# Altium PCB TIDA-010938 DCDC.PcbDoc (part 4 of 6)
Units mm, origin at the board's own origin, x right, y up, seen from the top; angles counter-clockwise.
Board outline 280 x 174.95 mm, 4 copper layers (Top Layer, Layer 1, Layer 2, Bottom Layer), stack 1.787 mm thick; 409 components, 218 nets, 1371 pads, 2268 vias.
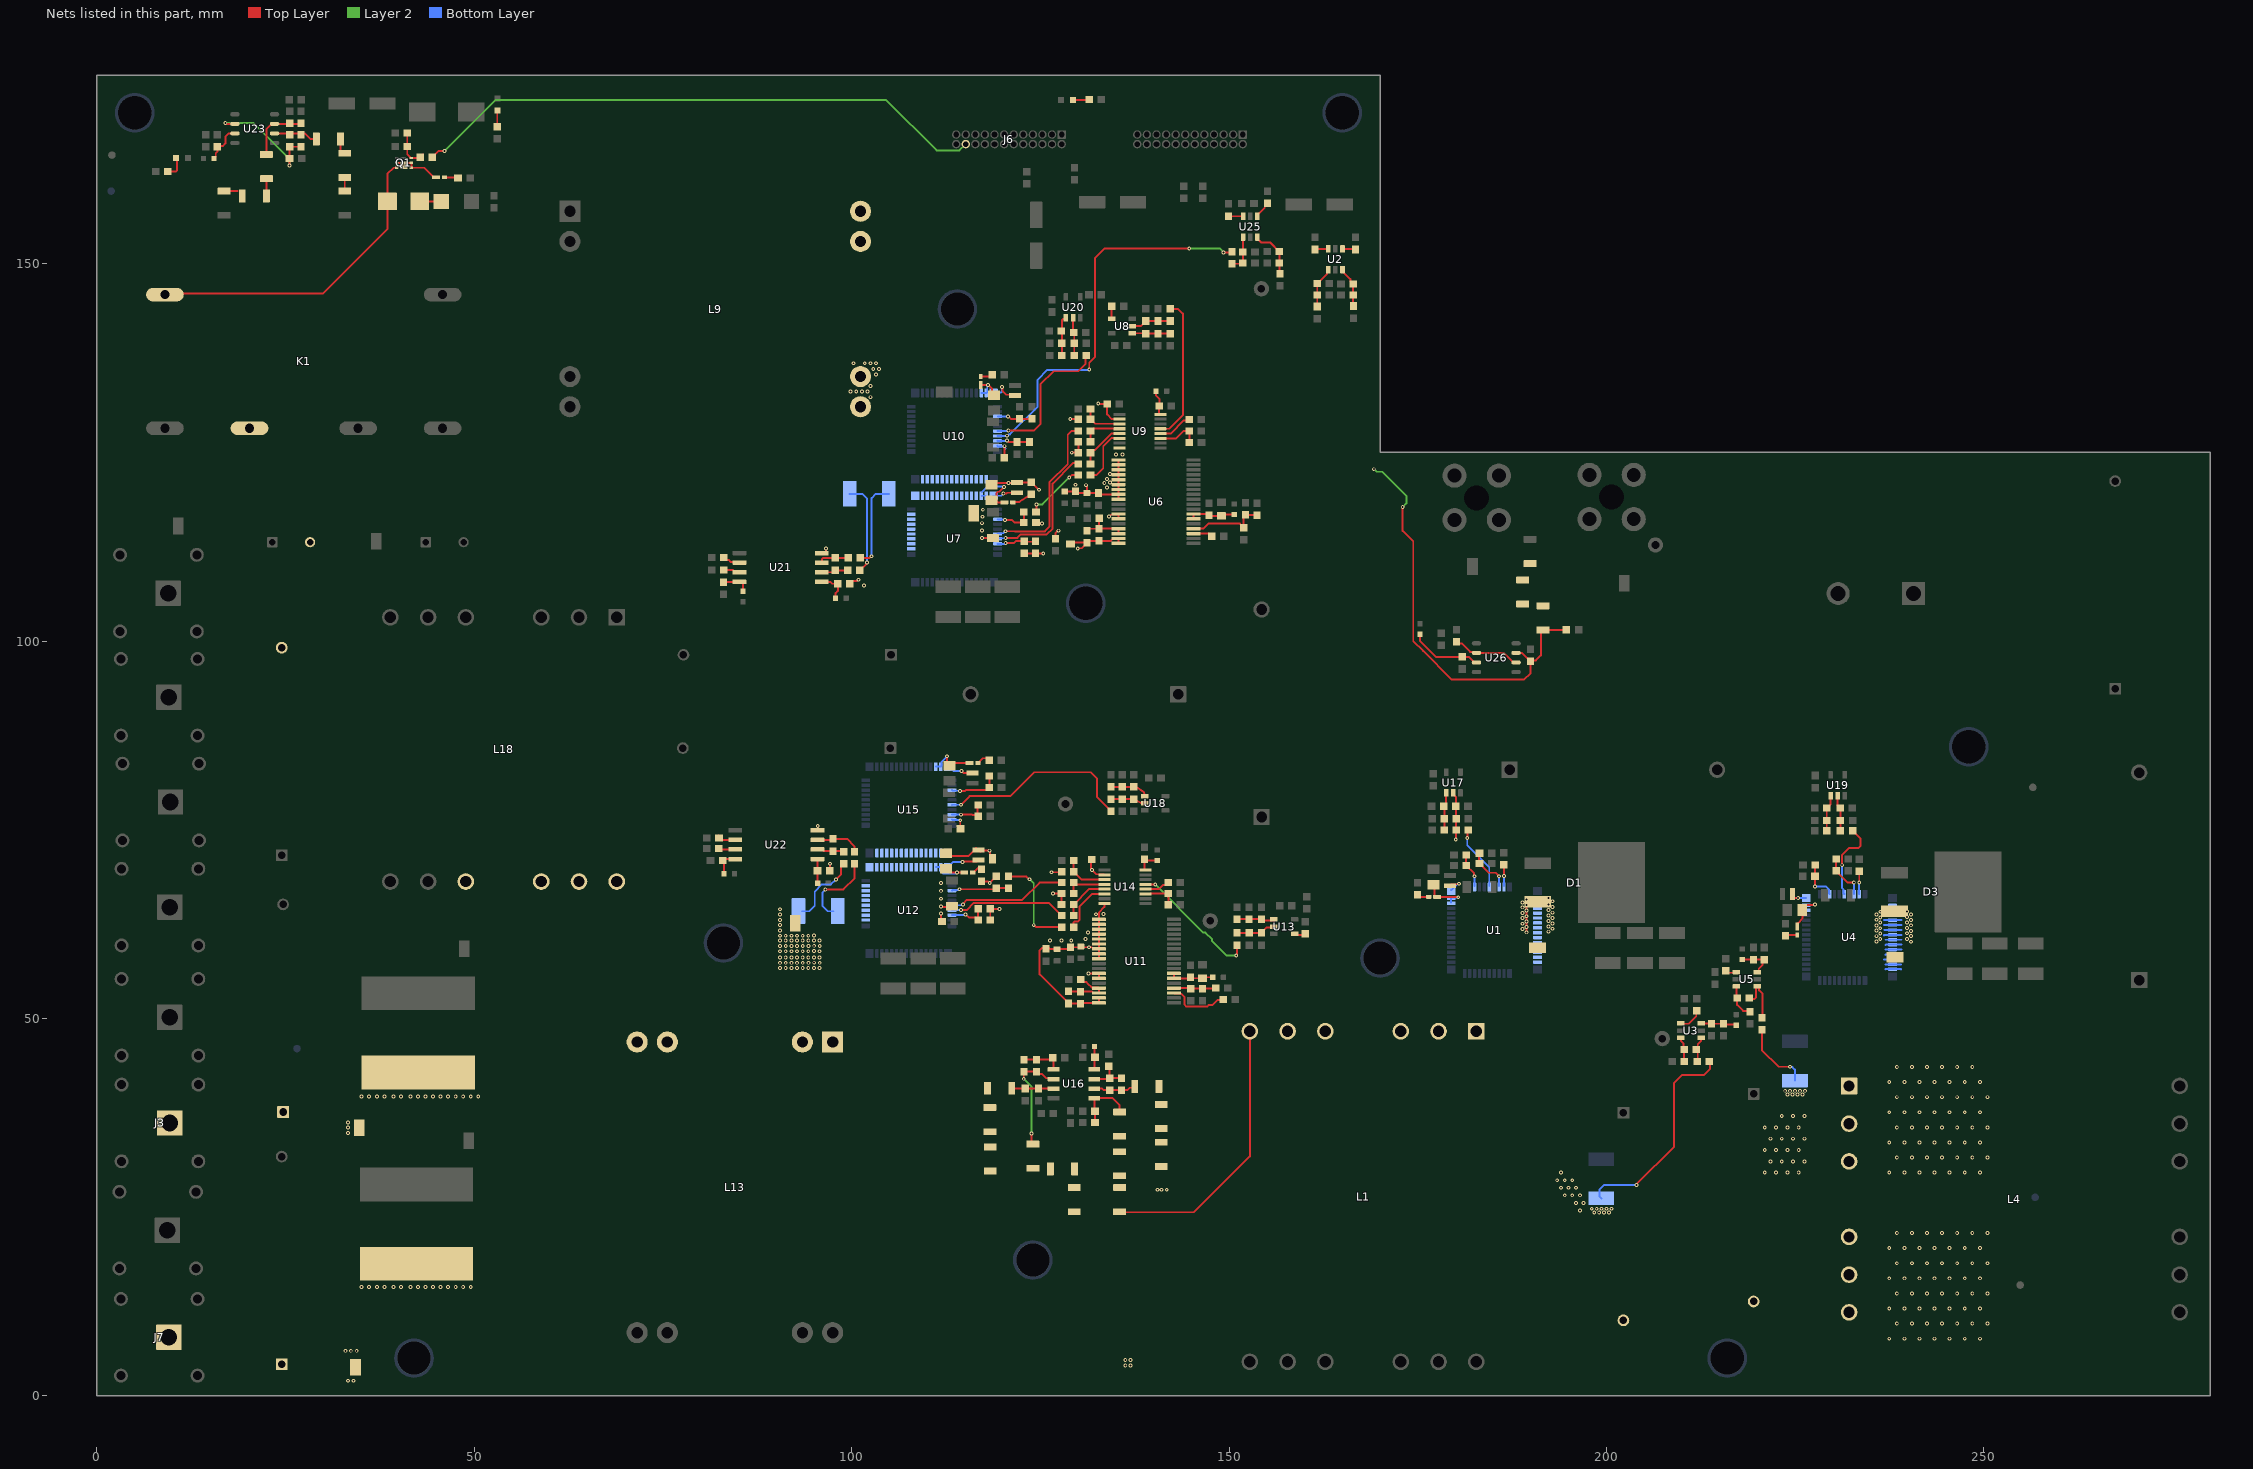
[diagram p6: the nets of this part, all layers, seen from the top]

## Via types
v1: diameter 0.508, hole 0.254, Top Layer to Bottom Layer, tented both sides, 1783 vias
v2: diameter 0.508, hole 0.254, Top Layer to Bottom Layer, 485 vias

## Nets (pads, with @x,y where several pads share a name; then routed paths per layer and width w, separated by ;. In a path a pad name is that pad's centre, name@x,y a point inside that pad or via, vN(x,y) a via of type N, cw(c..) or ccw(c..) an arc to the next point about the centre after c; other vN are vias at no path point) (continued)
IN_PWM_Bat_H1: R24.1 R38.2 | length 8.2
  Top Layer w0.254: R24.1@124.46,116.84 v1(124.46,118.11) ; v1(128.823,121.677) 128.836,121.677 129.158,122 R38.2@129.75,122
  Layer 2 w0.254: v1(124.46,118.11) 125.256,118.11 v1(128.823,121.677)
IN_PWM_Bat_H2: R49.1 R63.2 | length 13.1
  Top Layer w0.254: R49.1@120.494,68.865 R49.1@120.495,68.866 ; R49.1@120.754,68.785 123.155,68.785 123.492,68.449 v1(123.561,68.449) ; v1(124.116,62.355) 124.185,62.355 124.445,62.094 R63.2@127.804,62.094
  Layer 2 w0.254: v1(123.561,68.449) 124.116,67.893 v1(124.116,62.355)
NetC2_2: C2.2 K1.6 L18.9 L18.10 L18.11 L18.12 R88.2
NetC7_2: C7.2 R1.2 U1.45 | length 4.7
  Top Layer w0.254: R1.2@181.401,71.645 C7.2@181.401,70.262 181.426,70.262 182.477,69.211 182.477,68.885 v1(182.526,68.837)
  Bottom Layer w0.254: U1.45@182.526,67.517 v1(182.526,68.837) v1@182.526,68.934
NetC8_2: C8.2 U1.51 | length 2.9
  Top Layer w0.254: C8.2@186.392,70.365 186.426,70.331 v1(186.426,68.885)
  Bottom Layer w0.254: U1.51@186.426,67.517 v1(186.426,68.885)
NetC11_2: C11.2 R3.2 R39.2 U8.1 | length 5.1
  Top Layer w0.254: U8.1@137.189,140.785 138.931,140.785 C11.2@138.968,140.748 140.596,140.748 R3.2@142.259,140.748
NetC12_2: C12.2 R6.2 U1.50 | length 6
  Top Layer w0.254: R6.2@183.176,71.89 183.125,71.839 183.125,70.594 183.549,70.17 183.549,70.145 184.39,69.304 185.302,69.304 v1(185.769,68.836)
  Bottom Layer w0.254: v1(185.769,68.836) 185.773,68.833 185.773,67.52 U1.50@185.776,67.517
NetC13_1: C13.1 D17.1 U1.40 U1.41 | length 6.4
  Top Layer w0.254: C13.1@177.062,67.718 177.225,67.556 177.225,66.232 177.348,66.109 D17.1@177.571,66.109 177.596,66.084 180.341,66.084 v1(180.366,66.059)
  Bottom Layer w0.254: U1.40@179.416,65.367 U1.41@179.416,66.017 ; U1.41@179.416,66.007 179.459,65.964 179.502,66.007 180.245,66.007 180.297,66.059 v1(180.366,66.059)
NetC15_2: C15.2 R5.2 R64.2 U8.2 | length 5.3
  Top Layer w0.254: U8.2@137.189,141.735 138.318,141.735 138.968,142.385 138.968,142.41 R64.2@140.564,142.41 142.193,142.41 R5.2@142.195,142.411
NetC16_1: C16.1 Q1.3 R144.2 R145.1 | length 5.6
  Top Layer w0.254: R145.1@41.102,167.315 C16.1@41.102,165.52 41.102,164.482 41.569,164.016 Q1.3@41.644,164.016 42.866,164.016 R144.2@43.091,164.241 ; R144.2@42.802,164.111 42.827,164.111 R144.2@43.175,164.459
NetC17_1: C17.1 C108.2 FB1.2 U3.6 | length 4.5
  Top Layer w0.254: U3.6@212.575,49.35 213.85,49.35 C108.2@213.9,49.3 215.3,49.3 215.4,49.2 FB1.2@217,49.2
NetC18_1: C18.1 R10.2 U3.4 | length 3.4
  Top Layer w0.254: R10.2@212,44.3 212.1,44.4 212.1,46.6 212.5,47 212.5,47.375 U3.4@212.575,47.45
NetC18_2: C18.2 R9.2 U3.3 | length 3.3
  Top Layer w0.254: U3.3@209.825,47.45 209.9,47.375 209.9,47 210.222,46.678 210.222,45.978 C18.2@210.3,45.9 R9.2@210.3,44.3
NetC21_2: C21.2 U4.51 | length 3
  Top Layer w0.254: v1(233.5,68.006) C21.2@233.5,69.425
  Bottom Layer w0.254: U4.51@233.469,66.475 233.485,66.49 233.485,67.991 v1(233.5,68.006)
NetC22_2: C22.2 R11.2 U4.45 | length 5.5
  Top Layer w0.254: v1(227.625,67.488) 227.625,68.833 C22.2@227.629,68.837 227.629,70.3 R11.2@227.642,70.312
  Bottom Layer w0.254: v1(227.625,67.488) 229.069,67.488 229.471,67.086 229.471,66.573 U4.45@229.569,66.475
NetC25_2: C25.2 R13.2 R156.2 U13.1 | length 5.1
  Top Layer w0.254: R13.2@151.043,63.151 R156.2@152.66,63.151 C25.2@154.276,63.151 154.449,62.978 U13.1@156.055,62.978
NetC26_2: C26.2 R16.2 U4.50 | length 5.6
  Top Layer w0.254: C26.2@230.434,69.565 R16.2@230.434,71.111 ; C26.2@230.805,69.19 231.989,68.006 v1(232.775,68.006)
  Bottom Layer w0.254: v1(232.775,68.006) 232.797,67.984 232.797,66.497 U4.50@232.819,66.475
NetC27_1: C27.1 D18.1 U4.40 U4.41 | length 6.2
  Top Layer w0.254: D18.1@225.352,62.085 225.402,62.135 225.402,62.644 225.966,63.207 C27.1@225.966,64.365 225.966,64.53 226.474,65.038 227.357,65.038 227.409,65.09 v1@227.478,65.09
  Bottom Layer w0.254: U4.40@226.459,64.325 U4.41@226.459,64.975 226.525,65.041 227.429,65.041 v1@227.478,65.09
  other v1: 227.64,65.09
NetC29_2: C29.2 R15.2 R157.2 U13.2 | length 5.3
  Top Layer w0.254: R15.2@151.045,61.328 R157.2@152.661,61.328 C29.2@154.278,61.328 154.278,61.353 154.953,62.028 U13.2@156.055,62.028
NetC31_2: C31.2 C32.1 FB2.2 U5.6 | length 4.9
  Top Layer w0.254: FB2.2@218,57.8 C32.1@219.5,57.8 220.8,57.8 220.668,57.668 220.668,57.068 220.182,56.582 220.182,56.223 220.009,56.05 U5.6@219.975,56.05
NetC33_1: C33.1 R71.2 U5.4 | length 7
  Top Layer w0.254: C33.1@218.9,52.7 219,52.6 219.651,52.6 219.8,52.749 219.8,54.077 220.227,54.077 220.227,53.718 220.7,53.245 220.7,50.2 R71.2@220.6,50.1
NetC33_2: C33.2 R20.2 U5.3 | length 4.5
  Top Layer w0.254: U5.3@217.225,54.15 217.225,52.775 C33.2@217.3,52.7 217.3,51.8 218.1,51 218.9,51 R20.2@219,51.1
NetC35_2: C35.2 R24.2 U7.45 | length 5
  Top Layer w0.254: v1(120.319,116.034) 121.25,116.034 121.583,115.702 C35.2@122.818,115.702 ; C35.2@122.818,115.758 R24.2@122.818,117.117
  Bottom Layer w0.254: U7.45@119.333,116.144 119.36,116.117 120.293,116.117 v1@120.319,116.091
NetC39_2: C39.2 C43.2 FB4.2 U6.6 U6.7 | length 5.9
  Top Layer w0.254: U6.6@145.299,116.19 U6.7@145.299,116.84 147.178,116.84 147.328,116.69 147.428,116.59 C39.2@148.966,116.59 149.166,116.79 FB4.2@150.383,116.79
NetC42_1: C42.1 R23.2 R29.1 U6.33 U6.34 | length 6.3
  Top Layer w0.254: R29.1@131.18,114.884 C42.1@132.78,114.884 ; R23.2@132.78,116.39 C42.1@132.78,114.884 ; U6.34@135.349,114.24 U6.33@135.349,114.89 132.785,114.89 C42.1@132.78,114.884
NetC44_1: C44.1 R58.2 U21.2 | length 3.5
  Top Layer w0.254: U21.2@96.028,109.124 97.537,109.124 C44.1@97.825,109.412 ; C44.1@97.988,109.594 98.208,109.374 R58.2@99.465,109.374
NetC44_2: C44.2 R56.2 U21.3 | length 4.1
  Top Layer w0.254: U21.3@96.028,110.394 96.052,110.418 96.052,110.863 96.201,111.012 C44.2@97.825,111.012 99.52,111.012 R56.2@99.556,111.048
NetC45_2: C45.2 R32.2 U7.50 | length 4.7
  Top Layer w0.254: v1(120.397,112.975) 121.48,112.975 121.757,113.251 122.801,113.251 C45.2@122.846,113.206 ; C45.2@122.856,113.161 R32.2@123.892,113.161
  Bottom Layer w0.254: U7.50@119.333,112.894 119.341,112.886 120.239,112.886 120.328,112.975 v1(120.397,112.975)
NetC46_1: C46.1 D19.1 U7.40 U7.41 | length 8
  Top Layer w0.254: C46.1@118.535,118.667 118.581,118.667 118.924,119.01 119.009,119.01 119.174,119.175 119.174,119.619 119.342,119.787 119.541,119.787 v2(120.159,120.404) ; C46.1@118.983,118.95 118.983,118.883 119.208,118.659 119.208,118.525 119.357,118.376 D19.1@120.234,118.376
  Bottom Layer w0.254: U7.40@117.249,119.749 117.977,120.477 119.906,120.477 119.931,120.453 120.11,120.453 v2(120.159,120.404) ; U7.40@117.25,119.25 117.254,119.254 U7.41@117.825,119.254
NetC47_2: C47.2 R25.2 R27.2 U6.4 | length 10.3
  Top Layer w0.254: U6.4@145.299,114.89 146.605,114.89 147.296,115.58 151.392,115.58 151.56,115.413 151.585,115.413 C47.2@151.933,115.065 ; C47.2@151.933,115.04 C47.2@151.933,115.065 ; R27.2@153.431,116.69 153.416,116.705 151.948,116.705 151.933,116.69 C47.2@151.933,115.065
NetC48_1: C48.1 FB5.2 U21.1 | length 4.4
  Top Layer w0.254: U21.1@96.028,107.854 97.176,107.854 97.433,107.597 98.005,107.597 98.081,107.522 C48.1@98.156,107.597 98.156,106.649 97.863,106.356 FB5.2@97.863,105.681 ; FB5.2@98.009,105.609 FB5.2@98.081,105.681
NetC49_1: C49.1 FB12.2 U21.8 | length 3.7
  Top Layer w0.254: C49.1@83,107.8 83.054,107.854 85.408,107.854 85.581,107.681 FB12.2@85.581,106.608
NetC50_2: C50.2 FB9.2 U9.16 | length 3.4
  Top Layer w0.254: FB9.2@140.323,133.117 140.323,132.516 140.76,132.078 140.76,131.206 C50.2@140.716,131.162 140.716,130.115 140.794,130.037 U9.16@140.893,130.037
NetC53_1: C53.1 R96.2 U22.2 | length 3.6
  Top Layer w0.254: U22.2@95.464,72.39 96.064,72.39 96.275,72.18 C53.1@97.505,72.18 R96.2@98.945,72.18
NetC53_2: C53.2 R67.2 U22.3 | length 6.1
  Top Layer w0.254: U22.3@95.464,73.66 97.386,73.66 C53.2@97.505,73.78 99.384,73.78 100.36,72.804 100.36,72.445 100.522,72.283 R67.2@100.661,72.283
NetC54_2: C54.2 R155.1 U9.5 | length 5.8
  Top Layer w0.254: R155.1@131.639,123.463 C54.2@131.639,124.963 131.987,125.311 132.227,125.311 134.413,127.497 U9.5@134.864,127.497
NetC55_2: C55.2 R34.1 U9.3 | length 5.3
  Top Layer w0.254: R34.1@131.639,130.763 C55.2@131.639,129.389 131.664,129.389 132.254,128.8 U9.3@135.356,128.8
NetC56_1: C56.1 FB14.2 U22.1 | length 3.2
  Top Layer w0.254: FB14.2@95.451,67.923 95.451,69.547 C56.1@95.464,69.561 U22.1@95.464,71.12
NetC57_1: C57.1 FB13.2 U22.8 | length 3.8
  Top Layer w0.254: C57.1@82.839,71.12 U22.8@84.564,71.12 ; FB13.2@83.068,69.18 83.068,70.741 C57.1@82.889,70.92 C57.1@83.089,71.12
NetC58_2: C58.2 R37.2 U9.11 | length 5.8
  Top Layer w0.254: U9.11@140.893,126.862 142.986,126.862 143.981,127.857 C58.2@144.731,127.857 144.744,127.845 R37.2@144.744,126.319
NetC61_2: C61.2 U10.51 | length 2.6
  Top Layer w0.254: C61.2@120.1,124.563 120.238,124.701 v1(120.238,125.823)
  Bottom Layer w0.254: U10.51@119.28,125.902 119.409,125.773 120.133,125.773 120.412,125.493
NetC62_2: C62.2 R40.2 U10.45 | length 4.7
  Top Layer w0.254: v1(120.704,129.767) 120.772,129.767 121.14,129.399 123.807,129.399 R40.2@123.865,129.457
  Bottom Layer w0.254: U10.45@119.354,129.771 119.356,129.769 120.702,129.769 v1(120.704,129.767)
NetC63_1: C63.1 R100.2 R104.1 U16.6 | length 5.6
  Top Layer w0.254: U16.6@132.144,40.703 133.195,40.703 133.398,40.5 C63.1@134.181,40.5 136.5,40.5 136.818,40.818 137.318,40.818 R100.2@137.5,41
NetC63_2: C63.2 R87.1 R104.2 U16.7 | length 5.3
  Top Layer w0.254: U16.7@132.144,41.973 134.053,41.973 C63.2@134.181,42.1 ; R87.1@134.064,43.653 134.181,43.536 C63.2@134.181,42.1 ; R104.2@135.75,42.1 C63.2@134.181,42.1
NetC64_2: C64.2 R45.2 U10.50 | length 4.3
  Top Layer w0.254: v1@120.584,126.555 120.639,126.555 120.819,126.376 R45.2@123.555,126.376
  Bottom Layer w0.254: U10.50@119.28,126.552 119.294,126.538 120.553,126.538 v1(120.571,126.555)
NetC65_1: C65.1 D20.1 U10.40 U10.41 | length 4.4
  Top Layer w0.254: D20.1@117.091,133.931 v1(118.065,133.931) 118.118,133.931 118.593,133.456 118.593,132.834 C65.1@118.837,132.589
  Bottom Layer w0.254: U10.40@117.214,132.881 117.864,132.881 117.962,132.979 117.962,133.759 118.065,133.862 v1(118.065,133.931)
NetC66_1: C66.1 R103.2 R107.1 U16.2 | length 14.4
  Top Layer w0.254: v1(122.795,42) 122.795,42.92 R107.1@122.825,42.95 C66.1@124.5,42.95 124.828,42.622 125.225,42.622 125.771,42.075 126.642,42.075 U16.2@126.744,41.973 ; v1(123.825,34.75) 123.825,33.525 R103.2@124,33.35
  Layer 2 w0.254: v1(122.795,42) 123.825,40.97 v1(123.825,34.75)
NetC66_2: C66.2 R86.1 R107.2 U16.1 | length 5.5
  Top Layer w0.254: R107.2@122.825,44.55 C66.2@124.5,44.55 126.412,44.55 R86.1@126.654,44.793 126.744,44.703 U16.1@126.744,43.243
NetC67_1: C67.1 R75.2 R79.2 U17.1 | length 5
  Top Layer w0.254: R75.2@178.515,74.959 R79.2@178.515,76.459 178.515,78.105 178.76,78.35 U17.1@178.76,79.878
NetC69_2: C69.2 R49.2 U12.45 | length 7.2
  Top Layer w0.254: v1(114.287,67.114) 119.01,67.114 C69.2@119.152,67.256 120.381,67.256 R49.2@120.389,67.265
  Bottom Layer w0.254: U12.45@113.287,66.939 113.385,67.037 114.141,67.037 114.219,67.114 v1(114.287,67.114)
NetC73_2: C73.2 C77.2 FB6.2 U11.6 U11.7 | length 6
  Top Layer w0.254: U11.7@142.687,55.97 U11.6@142.687,55.32 144.747,55.32 C77.2@144.887,55.46 145.02,55.327 C73.2@146.497,55.327 146.63,55.46 FB6.2@147.837,55.46
NetC76_1: C76.1 R48.2 R54.1 U11.33 U11.34 | length 7.6
  Top Layer w0.254: R54.1@128.724,53.583 130.299,53.583 C76.1@130.324,53.558 131.848,53.558 132.037,53.37 U11.34@132.737,53.37 U11.33@132.737,54.02 132.639,54.118 131.776,54.118 131.299,54.595 131.045,54.849 130.634,54.849 R48.2@130.337,55.147
NetC78_1: C78.1 R76.2 R80.2 U18.1 | length 5.1
  Top Layer w0.254: R76.2@134.333,80.694 R80.2@135.833,80.694 137.333,80.694 137.681,80.651 137.762,80.651 138.675,80.002 138.747,79.93 138.793,79.657 138.793,79.636 U18.1@138.826,79.463
NetC79_2: C79.2 R57.2 U12.50 | length 5.3
  Top Layer w0.254: v1(115.066,63.76) 115.135,63.76 115.512,63.382 116.407,63.382 C79.2@116.755,63.034 R57.2@116.755,64.532
  Bottom Layer w0.254: U12.50@113.287,63.689 113.323,63.724 115.03,63.724 v1(115.066,63.76)
NetC80_1: C80.1 D21.1 U12.40 U12.41 | length 6.1
  Top Layer w0.254: C80.1@112.514,69.847 113.022,69.339 v2@113.935,69.339 ; D21.1@114.789,69.329 v2(113.959,69.329) ; v2@113.935,69.339 113.959,69.362 v2(113.959,69.329) ; v2@113.935,69.339 113.925,69.329 v2(113.959,69.329) ; v2@113.935,69.339 113.949,69.339 v2(113.959,69.329)
  Bottom Layer w0.254: U12.40@111.137,70.049 U12.41@111.787,70.049 111.885,69.951 111.885,69.438 112.127,69.197 113.758,69.197 113.89,69.329 v2(113.959,69.329)
NetC81_2: C81.2 R50.2 R52.2 U11.4 | length 5.6
  Top Layer w0.254: U11.4@142.687,54.02 144.85,54.02 C81.2@144.912,53.957 R52.2@146.497,53.957 148.137,53.957 R50.2@148.212,54.032
NetC82_1: C82.1 R77.2 R81.2 U17.2 | length 6.3
  Top Layer w0.254: U17.2@179.71,79.878 179.71,79.678 180.077,79.311 180.077,78.105 R81.2@180.077,76.459 R77.2@180.077,74.959 180.077,73.727 v1@180.066,73.716
  other v1: 180.032,73.716
NetC83_1: C83.1 R78.2 R82.2 U18.2 | length 4.6
  Top Layer w0.254: R78.2@134.333,79.069 R82.2@135.833,79.069 137.333,79.069 137.681,78.865 C83.1@137.72,78.865 ; C83.1@137.378,79.069 U18.2@138.408,78.504
NetC84_2: C84.2 FB10.2 U14.16 | length 3.2
  Top Layer w0.254: U14.16@138.916,69.668 138.878,69.668 138.8,69.746 C84.2@138.8,71.068 138.944,70.925 FB10.2@140.464,70.925
NetC86_1: C86.1 R83.2 R90.2 U19.1 | length 4.9
  Top Layer w0.254: R83.2@229.185,74.863 R90.2@229.185,76.244 C86.1@229.185,77.863 229.21,77.863 229.558,78.211 229.558,78.236 229.69,78.368 U19.1@229.69,79.513
NetC87_1: C87.1 R84.2 R91.2 U20.1 | length 5.4
  Top Layer w0.254: R84.2@127.825,137.837 127.851,137.863 127.851,142.536 128,142.685 128.223,142.685 U20.1@128.383,142.845
NetC88_2: C88.2 R158.1 U14.5 | length 6.4
  Top Layer w0.254: R158.1@129.4,63.623 129.396,63.627 C88.2@129.396,65.097 131.427,67.128 U14.5@133.491,67.128
NetC89_2: C89.2 R59.1 U14.3 | length 6
  Top Layer w0.254: R59.1@129.404,70.94 C89.2@129.404,69.448 130.454,68.398 U14.3@133.491,68.398
NetC90_2: C90.2 R35.1 U9.4 | length 5.3
  Top Layer w0.254: C90.2@131.639,126.414 R35.1@131.639,127.43 ; R35.1@131.639,127.854 R35.1@131.639,127.43 ; U9.4@134.976,128.14 132.012,128.14 131.864,127.992 131.864,127.655 R35.1@131.639,127.43
NetC91_1: C91.1 R85.2 R92.2 U19.2 | length 4.8
  Top Layer w0.254: U19.2@230.64,79.513 230.64,78.211 230.988,77.863 231.007,77.863 R92.2@231.007,76.244 R85.2@231.007,74.863
NetC92_2: C92.2 R62.2 U14.11 | length 4.4
  Top Layer w0.254: U14.11@138.941,66.493 138.969,66.521 139.598,66.521 139.613,66.536 C92.2@141.838,66.536 ; R62.2@141.974,65.008 C92.2@141.974,66.475
NetC95_2: C95.2 U15.51 | length 2.3
  Top Layer w0.254: v1(114.381,76.263) 114.381,75.471 114.494,75.358 C95.2@114.494,75.123
  Bottom Layer w0.254: U15.51@113.287,76.356 113.334,76.309 114.334,76.309 v1(114.381,76.263)
NetC96_2: C96.2 R65.2 U15.45 | length 6.7
  Top Layer w0.254: v1(114.361,80.122) 114.367,80.129 114.996,80.129 115.123,80.256 116.237,80.256 116.245,80.263 117.895,80.263 R65.2@118.243,80.611 C96.2@118.243,82.113
  Bottom Layer w0.254: U15.45@113.287,80.256 113.372,80.171 114.312,80.171 v1(114.361,80.122)
NetC97_1: C97.1 R89.2 R93.2 U20.2 | length 4.9
  Top Layer w0.254: U20.2@129.333,142.528 129.333,140.942 129.483,140.792 129.483,139.236 R89.2@129.483,137.736
NetC98_2: C98.2 R70.2 U15.50 | length 5.3
  Top Layer w0.254: v1(114.494,76.997) 114.543,77.046 115.92,77.046 116.023,76.943 116.611,76.943 C98.2@116.755,76.799 ; C98.2@116.488,76.483 116.687,76.682 116.687,77.775 R70.2@116.488,77.975
  Bottom Layer w0.254: U15.50@113.287,77.006 113.292,77.001 114.49,77.001 v1(114.494,76.997)
NetC99_1: C99.1 D22.1 U15.40 U15.41 | length 6.5
  Top Layer w0.254: v1(112.606,84.736) 112.606,83.847 C99.1@112.946,83.506 113.275,83.835 D22.1@115.537,83.835
  Bottom Layer w0.254: U15.40@111.137,83.366 U15.41@111.787,83.366 111.885,83.464 111.885,83.976 112.606,84.697 v1(112.606,84.736)
NetC102_2: C102.2 FB3.2 U16.8 | length 3.1
  Top Layer w0.254: U16.8@132.144,43.243 132.144,44.778 C102.2@132.234,44.868 132.168,44.934 FB3.2@132.168,46.272
NetC103_2: C103.2 R42.2 R106.1 U16.5 | length 8.7
  Top Layer w0.254: R106.1@132.234,36.222 C103.2@132.234,37.697 ; C103.2@132.234,37.787 132.144,37.787 U16.5@132.144,39.433 134.567,39.433 135.5,38.5 R42.2@135.5,37.6 ; R42.2@134.767,37.683 135.1,37.35 R42.2@135.5,37.35
NetC104_2: C104.2 R53.2 R139.1 U23.3 | length 8.3
  Top Layer w0.254: R53.2@22.442,164.473 22.442,167.802 23.175,168.535 U23.3@23.525,168.535 26.957,168.535 R139.1@27.031,168.608
NetC105_2: C105.2 R31.2 R140.2 U16.3 | length 5.9
  Top Layer w0.254: R31.2@121.005,41.11 121.398,40.718 R140.2@122.987,40.718 C105.2@124.745,40.718 124.76,40.703 U16.3@126.744,40.703
NetC107_2: C107.2 FB7.2 U26.7 | length 9.5
  Top Layer w0.254: FB7.2@175.3,100.9 175.3,100 177.4,97.9 C107.2@180.9,97.9 181.756,97.9 182.491,97.165 U26.7@182.775,97.165
NetC109_1: C109.1 R74.2 R141.1 U23.2 | length 5.8
  Top Layer w0.254: U23.2@23.525,167.265 27.535,167.265 28.268,166.532 R74.2@29.066,166.532
NetC109_2: C109.2 R141.2 R152.1 U23.6 | length 16.6
  Top Layer w0.254: v1(16.999,168.658) 17.122,168.535 U23.6@18.275,168.535 ; v1(25.5,163.024) 25.5,163.894 25.533,163.927 C109.2@25.533,165.495 R141.2@27.031,165.495
  Layer 2 w0.254: v1(16.999,168.658) 20.719,168.658 25.5,163.877 v1(25.5,163.024)
NetC116_2: C116.2 R109.2 R131.2 U2.1 | length 5.5
  Top Layer w0.254: R109.2@161.684,144.33 R131.2@161.684,145.864 C116.2@161.684,147.367 161.709,147.367 162.953,148.611 162.953,149.035 U2.1@163.126,149.208
NetC118_2: C118.2 R112.2 R129.2 U2.3 | length 5.4
  Top Layer w0.254: U2.3@165.026,149.208 165.026,149.008 166.061,147.973 166.061,147.681 166.409,147.333 C118.2@166.426,147.333 R129.2@166.426,145.869 166.426,144.462 R112.2@166.49,144.398
NetC120_2: C120.2 R117.2 R127.2 U25.1 | length 4.9
  Top Layer w0.254: R117.2@150.382,150 151.723,150 R127.2@151.83,150.108 C120.2@151.83,151.569 151.867,151.606 U25.1@151.867,153.488
NetC122_2: C122.2 R120.2 R125.2 U25.3 | length 6.8
  Top Layer w0.254: U25.3@153.755,153.536 153.755,153.336 154.28,152.811 155.433,152.811 156.644,151.6 C122.2@156.669,151.6 R125.2@156.669,150.108 156.669,148.735 R120.2@156.733,148.672
NetC123_2: C123.2 R12.1 R41.2 U26.3 | length 56.3
  Top Layer w0.254: v1(173,117.75) 173,114.6 174.4,113.2 174.4,100 175.7,98.7 179.5,94.9 189.069,94.9 189.939,95.77 C123.2@189.939,97.325 ; U26.3@188.025,98.435 188.804,98.435 189.566,97.673 189.591,97.673 C123.2@189.939,97.325 ; R41.2@190.944,101.467 R41.2@191.019,101.392 ; R12.1@194.75,101.5 194.717,101.467 R41.2@191.586,101.467 191.3,101.181 191.3,98.1 190.646,97.446 190.085,97.446 C123.2@189.939,97.3 C123.2@189.939,97.325
  Layer 2 w0.254: v1(169.176,122.773) 169.245,122.773 169.579,122.439 170.319,122.439 173.5,119.258 173.5,118.25 v1(173,117.75)
NetC151_2: C151.2 R60.1 U14.4 | length 5.6
  Top Layer w0.254: C151.2@129.396,66.55 129.407,66.562 R60.1@129.407,68.004 129.648,67.763 U14.4@133.491,67.763
NetC155_2: C155.2 FB11.2 U23.7 | length 5.3
  Top Layer w0.254: FB11.2@15.511,163.954 15.734,164.177 15.734,164.604 15.961,164.831 15.961,165.467 C155.2@15.933,165.495 16.021,165.583 16.641,165.583 16.999,165.941 16.999,166.799 17.465,167.265 U23.7@18.275,167.265
NetD1_2: D1.2 L1.1 L1.2 L1.3 TP12.1 U1.2 U1.3 U1.4 U1.5 U1.6 U1.7 U1.8 U1.9 U1.10 U1.11 U1.12 U1.13 U1.14 U1.15 | length 4.4
  Top Layer w0.254: v1(189.402,61.411) 189.402,65.011 189.425,65.033 v1(189.425,65.771)
  other v1: 192.312,61.497 188.86,61.852 192.834,61.88 189.402,62.104 192.312,62.189 188.86,62.545 192.834,62.573 189.402,62.848 192.312,62.934 188.86,63.29 192.834,63.317 189.402,63.541 192.312,63.626 188.86,63.982 192.834,64.01 189.402,64.285 192.312,64.371 188.86,64.727 192.834,64.755 189.425,65.011 192.32,65.095 188.86,65.375 192.834,65.524 192.32,65.94
NetD3_2: D3.2 L4.1 L4.2 L4.3 TP16.1 U4.2 U4.3 U4.4 U4.5 U4.6 U4.7 U4.8 U4.9 U4.10 U4.11 U4.12 U4.13 U4.14 U4.15 | length 24.5
  Bottom Layer w0.254: 236.753,57.825 U4.13@237.909,57.825 238.981,57.825 ; 236.753,61.013 236.815,61.075 U4.8@237.909,61.075 239.117,61.075 239.122,61.08 ; 236.753,62.375 U4.6@237.909,62.375 239.122,62.375 ; 236.753,63.025 U4.5@237.909,63.025 239.122,63.025 ; 236.815,61.724 236.816,61.725 U4.7@237.909,61.725 239.096,61.725 239.122,61.751 ; 236.939,56.489 236.976,56.525 U4.15@237.909,56.525 239.006,56.525 239.042,56.489 ; 236.939,57.175 U4.14@237.909,57.175 239.042,57.175 ; 236.939,58.413 237.001,58.475 U4.12@237.909,58.475 238.976,58.475 239.042,58.541 ; 236.939,59.125 U4.11@237.909,59.125 239.096,59.125 ; 236.939,59.713 237.001,59.775 U4.10@237.909,59.775 239.069,59.775 ; 236.939,60.425 U4.9@237.909,60.425 239.069,60.425
  other v1: 240.349,60.16 235.76,60.174 236.278,60.518 239.84,60.545 235.76,60.899 240.349,60.904 236.278,61.262 239.84,61.29 240.349,61.597 235.76,61.644 236.278,61.955 239.84,61.982 235.76,62.337 240.349,62.342 236.278,62.699 239.84,62.727 240.349,63.034 235.76,63.081 236.278,63.392 239.84,63.42 235.76,63.774 240.349,63.779 236.278,64.136 239.84,64.164
  other v2: 237.473,29.566 239.473,29.566 241.473,29.566 243.473,29.566 245.473,29.566 247.473,29.566 249.473,29.566 238.473,31.566 240.473,31.566 242.473,31.566 244.473,31.566 246.473,31.566 248.473,31.566 250.473,31.566 237.473,33.566 239.473,33.566 241.473,33.566 243.473,33.566 245.473,33.566 247.473,33.566 249.473,33.566 238.473,35.566 240.473,35.566 242.473,35.566 244.473,35.566 246.473,35.566 248.473,35.566 250.473,35.566 237.473,37.566 239.473,37.566 241.473,37.566 243.473,37.566 245.473,37.566 247.473,37.566 249.473,37.566 238.473,39.566 240.473,39.566 242.473,39.566 244.473,39.566 246.473,39.566 248.473,39.566 250.473,39.566 237.473,41.566 239.473,41.566 241.473,41.566 243.473,41.566 245.473,41.566 247.473,41.566 249.473,41.566 238.473,43.566 240.473,43.566 242.473,43.566 244.473,43.566 246.473,43.566 248.473,43.566
NetD11_2: D11.2 D12.2 | length 2.8
  Top Layer w0.254: D11.2@42.769,158.262 D12.2@45.619,158.262
NetD13_1: D13.1 R147.2 | length 2
  Top Layer w0.254: R147.2@53.036,168.179 D13.1@53.036,170.162
NetD14_2: D14.2 R7.2 | length 1.7
  Top Layer w0.254: D14.2@46.2,161.45 47.741,161.45 R7.2@47.832,161.36
NetD15_1: D15.1 R153.2 | length 2.2
  Top Layer w0.254: D15.1@129.307,171.711 131.406,171.711 R153.2@131.47,171.775
NetD16_1: D16.1 R154.2 | length 3
  Top Layer w0.254: R154.2@9.369,162.22 10.461,162.22 10.61,162.369 10.61,163.875 D16.1@10.473,164.013
NetD17_2: D17.2 R105.2 | length 1.2
  Top Layer w0.254: R105.2@175.253,66.109 D17.2@176.456,66.109
NetD18_2: D18.2 R132.2 | length 1.6
  Top Layer w0.254: R132.2@223.705,60.96 223.825,61.08 D18.2@225.279,61.08
NetD19_2: D19.2 R133.2 | length 2.7
  Top Layer w0.254: D19.2@121.349,118.376 121.572,118.454 122.208,118.454 123.412,119.21 123.43,119.21 R133.2@123.778,119.44
NetD20_2: D20.2 R135.2 | length 1.6
  Top Layer w0.254: D20.2@117.091,135.046 118.385,135.046 R135.2@118.635,135.296
NetD21_2: D21.2 R136.2 | length 1.4
  Top Layer w0.254: D21.2@116.029,69.329 116.129,69.329 116.718,69.918 117.122,69.918 R136.2@117.122,69.848
NetD22_2: D22.2 R138.2 | length 1.9
  Top Layer w0.254: D22.2@116.724,83.835 116.824,83.835 116.947,83.958 116.947,84.058 117.366,84.476 117.922,84.476 R138.2@118.194,84.205
NetL2_2: L2.2 U1.42 | length 2.7
  Top Layer w0.254: L2.2@179.25,67.584 179.448,67.782 180.322,67.782 180.381,67.842 v1(180.45,67.842)
  Bottom Layer w0.254: U1.42@179.416,66.992 179.441,66.992 180.242,67.793 180.401,67.793 v1(180.45,67.842)
NetL5_2: L5.2 U4.42 | length 2.2
  Top Layer w0.254: L5.2@224.668,66.507 224.668,66.173 224.866,65.975 v1(225.404,65.975)
  Bottom Layer w0.254: v1@225.404,65.95 U4.42@226.459,65.95
NetL7_2: L7.2 U7.42 | length 3.3
  Top Layer w0.254: v2@120.087,119.561 120.531,119.561 120.628,119.658 L7.2@121.873,119.658
  Bottom Layer w0.254: U7.42@118.808,119.254 119.812,119.254 120.087,119.53 v2@120.087,119.561
  other v2: 120.087,119.546
NetL9_5: L9.5 L9.6 L9.7 L9.8 R58.1 R134.1 | length 12.5
  Top Layer w0.254: R58.1@101.065,109.374 101.09,109.374 101.979,110.263 101.979,110.364 v1(102.027,110.413)
  Bottom Layer w0.254: R134.1@99.73,119.51 101.392,119.51 102,118.902 102,110.44 v1(102.027,110.413)
  other v2: 102.473,132.317 99.848,133.067 100.598,133.067 101.348,133.067 102.098,133.067 102.473,133.817 103.223,135.317 102.848,136.067 103.598,136.067 100.223,136.817 101.723,136.817 102.473,136.817 103.223,136.817
NetL10_2: L10.2 U10.42 | length 4.4
  Top Layer w0.254: v1(119.919,133.683) 119.967,133.635 119.967,133.139 120.47,132.636 121.539,132.636 L10.2@121.651,132.524
  Bottom Layer w0.254: U10.42@118.755,132.912 119.77,132.912 119.919,133.061 v1(119.919,133.683)
NetL11_2: L11.2 U12.42 | length 4.4
  Top Layer w0.254: v2(114.668,70.748) 114.717,70.796 116.599,70.796 L11.2@116.793,70.99
  Bottom Layer w0.254: U12.42@112.762,70.049 112.762,70.074 113.436,70.748 v2(114.668,70.748)
NetL13_1: L13.1 L13.2 L13.3 L13.4 R96.1 R137.1 TP10.1 | length 9.7
  Top Layer w0.254: v1(97.9,68.4) 98.597,69.097 98.597,70.125 R96.1@98.825,70.353
  Bottom Layer w0.254: R137.1@93.4,64.2 94.4,64.2 95.1,64.9 95.1,66.8 96.053,67.753 97.253,67.753 v1(97.9,68.4)
  other v1: 90.5,56.671 91.25,56.671 92,56.671 92.752,56.671 93.5,56.671 94.25,56.671 95.018,56.684 95.75,56.671 90.508,57.374 91.258,57.374 92.008,57.374 92.759,57.374 93.508,57.374 94.258,57.374 95.025,57.387 95.758,57.374 90.5,58.074 91.25,58.074 92,58.074 92.752,58.074 93.5,58.074 94.25,58.074 95.75,58.074 95.018,58.086 90.5,58.908 91.25,58.908 92,58.908 92.752,58.908 93.5,58.908 94.25,58.908 95.018,58.921 95.75,58.908 90.508,59.611 91.258,59.611 92.008,59.611 92.759,59.611 93.508,59.611 94.258,59.611 95.025,59.624 95.758,59.611 90.5,60.311 91.25,60.311 92,60.311 92.752,60.311 93.5,60.311 94.25,60.311 95.75,60.311 95.018,60.324 90.5,60.96 91.25,60.96 92,60.96 92.752,60.96 93.5,60.96 94.25,60.96 95.018,60.973 90.508,61.663 90.5,62.363 90.5,63.063 90.508,63.766 90.5,64.466
NetL14_2: L14.2 U15.42 | length 3.6
  Top Layer w0.254: v1(114.559,82.772) 114.586,82.772 114.842,82.515 L14.2@116.023,82.515
  Bottom Layer w0.254: U15.42@112.762,83.366 112.762,83.341 113.185,82.918 113.4,82.918 113.546,82.772 v1(114.559,82.772)
NetR4_1: R4.1 U8.4 | length 1.7
  Top Layer w0.254: R4.1@134.436,144.367 134.439,144.363 U8.4@134.439,142.685
NetR8_1: R8.1 U3.1 | length 3.3
  Top Layer w0.254: U3.1@209.825,49.35 209.875,49.3 210.9,49.3 211.9,50.3 R8.1@211.9,51.1
NetR14_1: R14.1 U13.4 | length 1.6
  Top Layer w0.254: U13.4@158.805,61.078 R14.1@160.403,61.078
NetR19_1: R19.1 U5.1 | length 1.5
  Top Layer w0.254: R19.1@215.8,56.3 216.05,56.05 U5.1@217.225,56.05
NetR21_2: R21.2 R26.1
NetR22_2: R22.2 U6.3 | length 2.6
  Top Layer w0.254: U6.3@145.299,114.24 146.719,114.24 146.725,114.234 147.372,114.234 R22.2@147.72,113.886
NetR26_2: R26.2 R41.1
NetR28_2: R28.2 R30.1 | length 0.1
  Top Layer w0.254: R28.2@118.365,32.978 R28.2@118.401,33.015
NetR30_2: R30.2 R31.1
NetR33_2: R33.2 R36.1 | length 0.3
  Top Layer w0.254: R36.1@135.198,28.823 R36.1@135.309,28.933 ; R33.2@135.389,27.489 R33.2@135.5,27.6
NetR36_2: R36.2 R42.1
NetR38_1: R38.1 U9.6 | length 7
  Top Layer w0.254: R38.1@131.639,121.991 132.409,121.991 133.323,122.905 133.323,125.787 134.445,126.909 U9.6@134.931,126.909
NetR43_2: R43.2 R44.1 | length 1.8
  Top Layer w0.254: R43.2@16.836,159.625 18.603,159.625
NetR44_2: R44.2 R53.1 | length 1.9
  Top Layer w0.254: R53.1@22.294,161.422 R53.1@22.442,161.273 22.454,161.261 R44.2@22.454,159.539
NetR46_1: R46.1 U26.2 U26.6 | length 9.1
  Top Layer w0.254: R46.1@180.1,99.9 180.307,99.693 180.807,99.693 181.935,98.565 182.215,98.565 182.345,98.435 186.405,98.435 187.675,97.165 U26.2@188.025,97.165
NetR47_2: R47.2 U11.3 | length 8.2
  Top Layer w0.254: U11.3@142.687,53.37 142.785,53.272 143.647,53.272 144.093,52.826 144.093,51.81 144.322,51.58 147.087,51.58 147.315,51.808 147.808,51.808 148.468,52.468 149.168,52.468 R47.2@149.2,52.5
NetR51_2: R51.2 U9.12 | length 4.6
  Top Layer w0.254: U9.12@140.893,127.497 142.247,127.497 143.986,129.236 144.602,129.236 R51.2@144.719,129.353
NetR61_2: R61.2 U21.6 | length 2.4
  Top Layer w0.254: R61.2@83.047,111.087 83.386,110.747 83.713,110.747 83.996,110.464 85.059,110.464 U21.6@85.128,110.394
NetR63_1: R63.1 U14.6 | length 7.3
  Top Layer w0.254: R63.1@129.404,62.094 129.392,62.611 129.392,62.614 cw(c129.646,62.617) 129.392,62.617 129.392,62.722 129.467,62.797 129.541,62.871 130.014,62.871 130.177,63.033 130.177,64.821 131.82,66.465 133.463,66.465 U14.6@133.491,66.493
NetR66_2: R66.2 U21.7 | length 2.2
  Top Layer w0.254: R66.2@83.047,109.43 84.223,109.43 84.528,109.124 U21.7@85.128,109.124
NetR68_2: R68.2 R69.1 | length 1.8
  Top Layer w0.254: R68.2@32.825,159.625 R69.1@32.825,161.441
NetR69_2: R69.2 R74.1 | length 2.3
  Top Layer w0.254: R74.1@32.266,166.532 32.266,164.964 32.589,164.641 R69.2@32.825,164.641
NetR73_2: R73.2 U22.6 | length 2.5
  Top Layer w0.254: R73.2@82.342,74.22 82.342,74.106 82.788,73.66 U22.6@84.564,73.66
NetR94_2: R94.2 R98.1
NetR95_2: R95.2 U22.7 | length 2.4
  Top Layer w0.254: R95.2@82.342,72.75 82.702,72.39 U22.7@84.564,72.39
NetR98_2: R98.2 R100.1
NetR101_2: R101.2 R102.1
NetR102_2: R102.2 R103.1
NetR108_1: R108.1 U2.6 | length 1.8
  Top Layer w0.254: R108.1@161.385,151.883 161.46,151.958 U2.6@163.126,151.958
NetR113_1: R113.1 U2.4 | length 1.8
  Top Layer w0.254: U2.4@165.026,151.958 166.67,151.958 R113.1@166.745,151.883
NetR116_1: R116.1 U25.6 | length 2
  Top Layer w0.254: R116.1@149.907,156.319 149.94,156.286 U25.6@151.855,156.286
NetR121_1: R121.1 U25.4 | length 2
  Top Layer w0.254: U25.4@153.855,156.519 153.855,156.586 153.928,156.659 153.995,156.659 154.721,157.386 154.721,157.646 154.903,157.828 R121.1@155.163,157.828
NetR159_2: R159.2 U14.12 | length 3.3
  Top Layer w0.254: U14.12@138.941,67.128 140.695,67.128 141.239,67.672 141.54,67.672 141.838,67.97 R159.2@141.838,68.004
O\C\__Bat_H1_Buff: R5.1 U9.13 | length 18.8
  Top Layer w0.254: U9.13@140.893,128.132 140.894,128.133 142.074,128.133 143.869,129.928 143.869,143.381 143.25,144 R5.1@142.5,144
O\C\_Bat_H1_init: R35.2 U7.48 | length 22.1
  Top Layer w0.254: v1(120.381,114.55) 121.592,114.55 121.596,114.546 125.595,114.546 126.2,115.151 126.2,121.038 128.62,123.457 128.62,127.326 129.148,127.854 R35.2@130.039,127.854
  Bottom Layer w0.254: U7.48@119.333,114.194 119.431,114.292 120.054,114.292 120.312,114.55 v1(120.381,114.55)
O\C\_Bat_H2_Buff: R15.1 U14.13 | length 17.5
  Top Layer w0.254: U14.13@138.941,67.763 v1(140.212,67.763) ; v1(150.95,58.321) 150.95,58.389 151.045,58.484 R15.1@151.045,59.728
  Layer 2 w0.254: v1(140.212,67.763) 146.589,61.386 146.865,61.386 147.759,60.491 147.759,60.241 149.68,58.321 v1(150.95,58.321)
O\C\_Bat_H2_init: R60.2 U12.48 | length 15.8
  Top Layer w0.254: v1(114.745,65.119) 114.745,65.188 115.263,65.705 122.592,65.705 124.89,68.004 R60.2@127.807,68.004
  Bottom Layer w0.254: U12.48@113.287,64.989 113.302,65.003 114.561,65.003 114.677,65.119 v1(114.745,65.119)
O\C\_Bat_L1_init: R89.1 U10.48 | length 19.6
  Top Layer w0.254: v1(120.746,127.906) 124.156,127.906 125,128.75 125,134 126.75,135.75 130,135.75 131,136.75 131,137.756 R89.1@131.083,137.838
  Bottom Layer w0.254: U10.48@119.299,127.833 119.329,127.863 120.704,127.863 v1(120.746,127.906)
O\C\_Bat_L2_init: R78.1 U15.48 | length 26.5
  Top Layer w0.254: v1(114.494,78.315) 115.626,79.448 120.618,79.448 120.634,79.463 121.018,79.463 124.178,82.623 131.639,82.623 132.516,81.745 132.516,79.31 134.333,77.494 R78.1@134.333,77.469 R78.1@134.333,77.394
  Bottom Layer w0.254: U15.48@113.287,78.306 113.292,78.31 114.489,78.31 v1(114.494,78.315)
O\C\_Boost1_init: R77.1 U1.48 | length 8.7
  Top Layer w0.254: v1@181.593,73.892 181.593,74.875 R77.1@181.677,74.959
  Bottom Layer w0.254: v1(181.558,73.892) 181.558,72.942 184.476,70.024 U1.48@184.476,67.517
O\C\_Boost2_init: R85.1 U4.48 | length 10.7
  Top Layer w0.254: v1(231.232,70.309) 231.232,71.679 232.122,72.569 233.364,72.569 233.675,72.88 233.675,73.82 232.632,74.863 R85.1@232.607,74.863
  Bottom Layer w0.254: v1(231.232,70.309) 231.232,67.274 231.371,67.136 231.371,67.072 231.421,67.022 231.421,66.573 U4.48@231.519,66.475
"PV1 Bus+": C9.2 L1.4 L1.5 L1.6 L6.2 R33.1 | length 36.9
  Top Layer w0.254: R33.1@135.5,24.4 135.584,24.316 145.344,24.316 152.75,31.723 L1.6@152.75,48.3
  other v1: 35.025,39.646 36.018,39.646 37.08,39.646 38.074,39.646 39.275,39.646 40.268,39.646 41.525,39.646 42.518,39.646 43.525,39.646 44.518,39.646 45.525,39.646 46.518,39.646 47.525,39.646 48.518,39.646 49.525,39.646 50.518,39.646
"PV1 Bus-": C30.1 J3.1 R10.1 R17.1 R94.1 TP41.1 | length 28.5
  Top Layer w0.254: v1(203.963,27.95) 203.963,28.01 208.97,33.017 208.97,41.47 210,42.5 212.9,42.5 213.693,43.293 213.693,44.207 R10.1@213.6,44.3
  Bottom Layer w0.254: R17.1@199.331,26.15 199.063,26.418 199.063,27.282 199.731,27.95 v1(203.963,27.95)
  other v1: 198.385,24.276 199.035,24.276 199.685,24.276 200.335,24.276 198.055,24.784 198.705,24.784 199.355,24.784 200.005,24.784 200.673,24.784 140.495,27.308 141.061,27.308 141.745,27.308 33.239,34.827 33.25,35.534 33.239,36.225
  other v2: 196.473,24.566 195.973,25.566 196.973,25.566 194.473,26.566 195.473,26.566 196.473,26.566 193.973,27.566 194.973,27.566 195.973,27.566 193.473,28.566 194.473,28.566 195.473,28.566 193.973,29.566
"PV2 Bus+": C23.2 L4.4 L4.5 L4.6 L8.2 R28.1
  other v1: 35.025,14.414 36.018,14.414 37.08,14.414 38.074,14.414 39.275,14.414 40.268,14.414 41.525,14.414 42.518,14.414 43.525,14.414 44.518,14.414 45.525,14.414 46.518,14.414 47.525,14.414 48.518,14.414 49.525,14.414
  other v2: 237.473,7.566 239.473,7.566 241.473,7.566 243.473,7.566 245.473,7.566 247.473,7.566 249.473,7.566 238.473,9.566 240.473,9.566 242.473,9.566 244.473,9.566 246.473,9.566 248.473,9.566 250.473,9.566 237.473,11.566 239.473,11.566 241.473,11.566 243.473,11.566 245.473,11.566 247.473,11.566 249.473,11.566 238.473,13.566 240.473,13.566 242.473,13.566 244.473,13.566 246.473,13.566 248.473,13.566 250.473,13.566 237.473,15.566 239.473,15.566 241.473,15.566 243.473,15.566 245.473,15.566 247.473,15.566 249.473,15.566 238.473,17.566 240.473,17.566 242.473,17.566 244.473,17.566 246.473,17.566 248.473,17.566 250.473,17.566 237.473,19.566 239.473,19.566 241.473,19.566 243.473,19.566 245.473,19.566 247.473,19.566 249.473,19.566 238.473,21.566 240.473,21.566 242.473,21.566 244.473,21.566 246.473,21.566 248.473,21.566 250.473,21.566
"PV2 Bus-": C224.1 J7.1 R18.1 R71.1 R101.1 TP44.1 | length 9.6
  Top Layer w0.254: R71.1@220.6,48.5 220.6,45.8 222.8,43.6 v1(224.316,43.6)
  Bottom Layer w0.254: v1(224.316,43.6) 224.364,43.552 224.648,43.552 224.979,43.221 R18.1@224.979,41.76
  other v1: 33.247,2 33.997,2 136.25,4 136.956,4 136.25,4.75 136.956,4.75 32.924,5.96 33.629,5.96 34.409,5.96 224.009,39.906 224.659,39.906 225.309,39.906 225.959,39.906 223.679,40.414 224.329,40.414 224.979,40.414 225.629,40.414 226.297,40.414
  other v2: 220.973,29.566 222.473,29.566 223.973,29.566 225.473,29.566 221.723,31.066 223.223,31.066 224.723,31.066 226.223,31.066 220.973,32.566 222.473,32.566 223.973,32.566 225.473,32.566 221.723,34.066 223.223,34.066 224.723,34.066 226.223,34.066 220.973,35.566 222.473,35.566 223.973,35.566 225.473,35.566 223.223,37.066 224.723,37.066 226.223,37.066
RY_DCPreCharge: J6.22 R144.1 | length 77
  Top Layer w0.254: R144.1@44.402,164.111 44.427,164.111 45.273,164.957 v1(46.045,164.957)
  Layer 2 w0.254: v1(46.045,164.957) 52.771,171.683 104.559,171.683 111.232,165.009 114.273,165.009 J6.22@115.11,165.846
SN_DCPreCharge: D11.1 D14.1 K1.1 Q1.1 Q1.2 Q1.5 Q1.6 Q1.8 | length 47.2
  Top Layer w0.254: K1.1@10.425,146.05 29.925,146.05 38.469,154.594 D11.1@38.469,158.262 38.469,161.894 39.291,162.716 Q1.6@39.694,162.716 Q1.5@39.694,163.366 41.614,163.366 41.629,163.351 Q1.2@41.644,163.366 Q1.1@41.644,162.716 43.334,162.716 D14.1@44.6,161.45
SW1: C34.2 C35.1 C36.1 C37.1 C38.1 C40.2 C41.2 C42.2 C45.1 C46.2 C48.2 C51.1 C54.1 C55.1 C90.1 D6.2 L7.1 R29.2 R32.1 R56.1 R133.1 R134.2 TP9.1 U6.19 U6.20 U6.21 U6.22 U6.23 U6.24 U6.25 U6.26 U6.27 U6.30 U6.31 U6.35 U6.36 U7.18 U7.19 U7.20 U7.21 U7.22 U7.23 U7.24 U7.25 U7.27 U7.28 U7.29 U7.30 U7.31 U7.32 U7.33 U7.34 U7.35 U7.36 U7.37 U7.38 U7.39 U9.2 U9.8 U10.2 U10.3 U10.4 U10.5 U10.6 U10.7 U10.8 U10.9 U10.10 U10.11 U10.12 U10.13 U10.14 U10.15 U21.4 | length 59.7
  Top Layer w0.254: U21.4@96.028,111.664 96.439,111.664 96.612,111.837 v1(96.612,112.261) ; C48.2@99.756,107.597 C48.2@99.804,107.644 ; C48.2@100,107.75 100,107.815 100.129,107.945 100.634,107.945 100.81,108.121 v1(100.879,108.121) ; R56.1@101,111 102.318,111 102.562,111.245 v1(102.631,111.245) ; v2(117.245,113.666) 118.739,113.666 C34.2@118.742,113.662 ; C46.2@118.535,120.699 118.771,120.935 121.828,120.935 121.875,120.983 122.102,120.998 122.546,121.01 122.561,121.01 123.427,121.031 123.43,121.031 R133.1@123.778,121.04 123.778,121.015 124.697,120.096 124.78,120.096 v2(124.829,120.048) ; C45.1@122.856,111.615 R32.1@124.348,111.615 v1@125.353,111.615 ; C35.1@124.418,115.702 124.55,115.57 v1(125.219,115.57) ; C36.1@127,113.557 127,114.359 127.218,114.576 127.329,114.576 v1(127.378,114.625) ; C41.2@128.249,119.815 129.595,119.815 129.826,119.583 129.865,119.622 C37.1@132.705,119.622 132.887,119.44 U6.26@135.349,119.44 ; v1(128.949,129.415) 130.014,129.415 C55.1@130.039,129.389 ; D6.2@129,112.862 129.185,113.048 R29.2@131.18,113.048 ; v1(129.151,124.963) C54.1@130.039,124.963 C90.1@130.039,126.414 ; v1(129.953,112.25) 130.001,112.299 130.456,112.299 131.18,113.023 R29.2@131.18,113.048 ; v1(131.027,120.656) 131.027,120.588 131.18,120.435 131.18,119.658 C40.2@131.168,119.646 ; v1@132.705,131.465 132.739,131.431 C51.1@133.849,131.431 133.849,130.034 134.474,129.41 135.486,129.41 U9.2@135.493,129.402 ; v1(134.089,116.502) 134.158,116.502 134.398,116.742 135.251,116.742 U6.30@135.349,116.84 U6.31@135.349,116.19 ; U6.36@135.349,112.94 U6.35@135.349,113.59 134.649,113.59 134.344,113.284 C42.2@132.78,113.284 131.18,113.284 R29.2@131.18,113.048 ; U6.27@135.349,118.79 U6.26@135.349,119.44 ; U6.19@135.349,123.99 U6.20@135.349,123.34 U6.21@135.349,122.69 U6.22@135.349,122.04 U6.23@135.349,121.39 U6.24@135.349,120.74 U6.25@135.349,120.09 U6.26@135.349,119.44
  Bottom Layer w0.254: v1(102.631,111.245) 102.631,118.935 103.206,119.51 R134.2@104.93,119.51
  other v1: 101.63,107.37 125.379,111.615 133.819,120.331 129.646,120.715 133.468,120.924 120.75,120.957 134.235,120.99 133.819,121.468 134.235,122.127 135.01,124.721 135.856,124.736 132.662,131.496
  other v2: 117.281,114.668 117.281,115.621 117.336,116.469 117.371,117.396
SW2: C56.2 C68.2 C69.1 C70.1 C71.1 C72.1 C74.2 C75.2 C76.2 C79.1 C80.2 C85.1 C88.1 C89.1 C151.1 D9.2 L11.1 R54.2 R57.1 R67.1 R136.1 R137.2 U11.19 U11.20 U11.21 U11.22 U11.23 U11.24 U11.25 U11.26 U11.27 U11.30 U11.31 U11.35 U11.36 U12.18 U12.19 U12.20 U12.21 U12.22 U12.23 U12.24 U12.25 U12.27 U12.28 U12.29 U12.30 U12.31 U12.32 U12.33 U12.34 U12.35 U12.36 U12.37 U12.38 U12.39 U14.2 U14.8 U15.2 U15.3 U15.4 U15.5 U15.6 U15.7 U15.8 U15.9 U15.10 U15.11 U15.12 U15.13 U15.14 U15.15 U22.4 | length 66
  Top Layer w0.254: v2(95.5,75.5) 95.5,75.1 U22.4@95.6,75 ; v1(96.5,67.1) 98.89,67.1 100.378,68.588 R67.1@100.378,70.472 ; C56.2@97.064,69.561 97.103,69.6 v1(97.103,70.501) ; v2(111.834,63.918) 111.834,62.992 C70.1@111.962,62.863 ; v2@111.849,64.784 113.198,64.784 C68.2@113.287,64.874 ; C80.2@112.514,71.879 112.88,71.513 115.419,71.513 L11.1@116.473,72.566 ; L11.1@116.391,72.34 L11.1@116.793,72.34 ; L11.1@116.535,72.461 L11.1@116.609,72.461 ; L11.1@117.009,72.125 117.114,72.229 v1(118.248,72.229) 118.248,72.16 118.312,72.096 118.312,71.48 D9.2@118.642,71.15 ; L11.1@117.103,72.141 L11.1@117.161,72.199 ; R136.1@117.194,68.173 118.018,68.173 118.222,67.968 v1(118.284,67.968) 118.288,67.968 119.152,68.831 C69.1@119.152,68.856 ; C79.1@118.355,63.034 R57.1@118.355,64.532 118.408,64.48 v1(119.585,64.48) ; v1(126.458,69.372) 127.729,69.372 C89.1@127.804,69.448 ; v1(126.674,66.55) C151.1@127.796,66.55 C88.1@127.796,65.097 ; v1(131.374,55.941) 131.388,55.955 132.722,55.955 U11.30@132.737,55.97 U11.31@132.737,55.32 ; C85.1@131.716,71.15 131.716,69.868 131.848,69.736 v1(131.848,69.668) 132.405,69.111 133.413,69.111 U14.2@133.491,69.033 ; U11.35@132.737,52.72 U11.36@132.737,52.07 130.436,52.07 C76.2@130.324,51.958 128.749,51.958 R54.2@128.724,51.983 128.724,52.008 124.89,55.842 124.89,59.027 125.193,59.329 126.16,59.329 126.303,59.186 128.73,59.186 C71.1@128.972,59.428 v1(131.427,59.428) 131.828,59.428 132.037,59.22 U11.25@132.737,59.22 ; U11.27@132.737,57.92 U11.26@132.737,58.57 U11.25@132.737,59.22 ; U14.8@133.491,65.223 133.491,64.78 132.737,64.026 U11.19@132.737,63.12 U11.20@132.737,62.47 U11.21@132.737,61.82 U11.22@132.737,61.17 U11.23@132.737,60.52 U11.24@132.737,59.87 U11.25@132.737,59.22
  Bottom Layer w0.254: v1(96.5,67.1) 96.5,67.031 96.1,66.631 96.1,64.9 96.8,64.2 R137.2@97.6,64.2
  other v1: 126.276,60.344 127.785,60.344 129.082,60.344 130.975,60.52 131.299,61.369 132.373,63.807 133.344,63.832
  other v2: 111.806,64.811 111.806,65.862 111.806,66.913 111.806,67.964
TEMP_Bat_H1_init: R155.2 U7.49 | length 18.4
  Top Layer w0.254: v1(120.397,113.671) 121.945,113.671 122.415,114.142 125.842,114.142 126.604,114.904 126.604,120.87 129.307,123.573 129.929,123.573 R155.2@130.039,123.463
  Bottom Layer w0.254: U7.49@119.333,113.544 119.412,113.622 120.349,113.622 v1(120.397,113.671)
TEMP_Bat_H2_init: R158.2 U12.49 | length 15.6
  Top Layer w0.254: v1(114.491,64.354) 115.21,64.354 116.157,65.301 126.122,65.301 R158.2@127.8,63.623
  Bottom Layer w0.254: U12.49@113.287,64.339 113.295,64.346 114.484,64.346 v1(114.491,64.354)
TEMP_Bat_L1_init: R117.1 U10.49 | length 52
  Top Layer w0.254: v1(131.468,135.972) 131.468,136.857 132.259,137.647 132.259,150.759 133.521,152.021 144.709,152.021 v1(144.719,152.031) ; v1(149.27,151.505) 150.287,151.505 R117.1@150.382,151.6
  Layer 2 w0.254: v1(144.719,152.031) 144.729,152.021 148.754,152.021 v1(149.27,151.505)
  Bottom Layer w0.254: U10.49@119.321,127.173 119.34,127.192 120.558,127.192 v1(120.579,127.213) 120.648,127.213 120.809,127.375 120.966,127.375 124.617,131.025 124.617,134.617 125.93,135.93 131.43,135.93 v1@131.5,136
